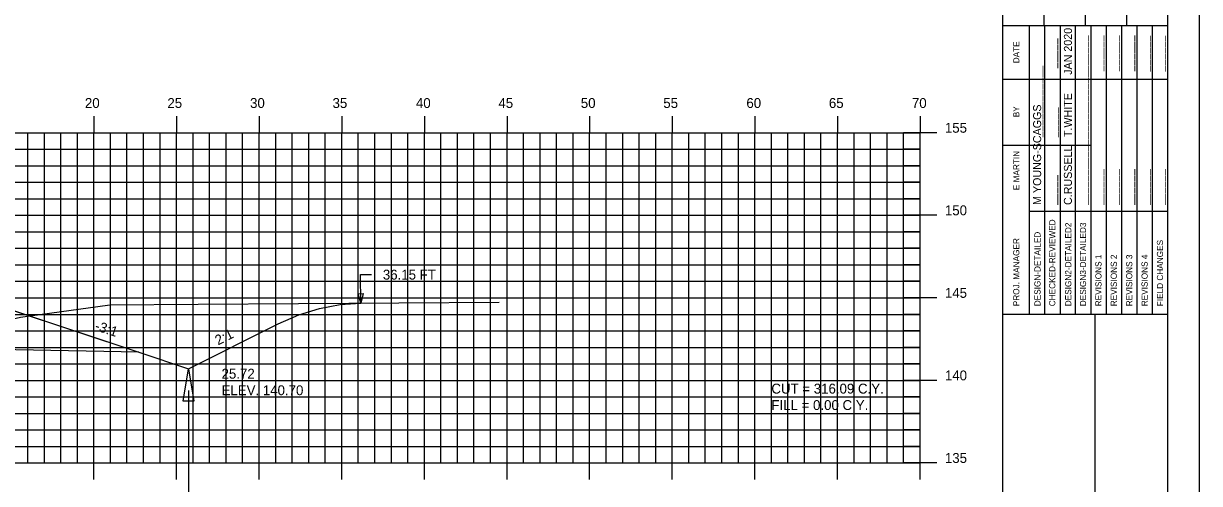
# Model space of a CAD drawing. Extents: x 1144972 to 1145142, y 608981 to 609091.
# Drawn here: x 1145071.1 to 1145142.3, y 609019.1 to 609047 of the extents above; entities that cross this region are included whole.
import ezdxf

# ---------------------------------------------------------------- set-up
doc = ezdxf.new("R2010")
doc.units = 0
for name, color, linetype in [('ANNOTATION', 7, 'Continuous'), ('BORDER', 7, 'Continuous'), ('D_Drainage_Ditch_Line', 7, 'Continuous'), ('D_Roadway_SlopeLines', 7, 'Continuous'), ('D_Roadway_SubGrade', 7, 'Continuous'), ('D_Text_Standard', 7, 'Continuous'), ('H_V ANNOTATION', 7, 'Continuous'), ('MAJOR', 7, 'Continuous'), ('MINOR', 7, 'Continuous'), ('PLOT BOUNDARY', 7, 'Continuous'), ('S_Roadway_Centerline', 7, 'Continuous')]:
    doc.layers.add(name, color=color, linetype=linetype)

msp = doc.modelspace()

# ---------------------------------------------------------------- linework, layer by layer
msp.add_lwpolyline([(1145018.151, 609030.592), (1145019.401, 609030.491), (1145020.651, 609030.24), (1145021.901, 609029.839), (1145023.151, 609029.289), (1145029.651, 609026.039), (1145032.651, 609027.039), (1145040.374, 609029.614), (1145040.375, 609029.614), (1145044.375, 609029.774), (1145055.375, 609029.994), (1145066.375, 609029.774), (1145070.375, 609029.614), (1145078.099, 609027.039), (1145081.099, 609026.039), (1145086.528, 609028.754), (1145087.778, 609029.302), (1145089.028, 609029.695), (1145090.278, 609029.934), (1145091.528, 609030.018)])
at = {"layer": 'BORDER'}
for p, q in [((1145130.376, 608984.335), (1145130.376, 609089.335)), ((1145132.876, 609046.838), (1145132.876, 609055.485)), ((1145135.376, 609046.838), (1145135.376, 609055.485)), ((1145137.876, 609046.838), (1145137.876, 609055.485)), ((1145130.376, 609046.838), (1145140.376, 609046.838)), ((1145130.376, 609029.338), (1145140.376, 609029.338)), ((1145135.967, 608994.338), (1145135.967, 609029.338))]:
    msp.add_line(p, q, dxfattribs=at)
msp.add_lwpolyline([(1144980.376, 608984.335), (1145140.376, 608984.335), (1145140.376, 609089.335), (1144980.376, 609089.335)], close=True, dxfattribs=at)
for points in [[(1145131.99, 609043.588), (1145131.99, 609046.838)], [(1145132.923, 609029.341), (1145132.923, 609046.838)], [(1145133.855, 609046.838), (1145133.855, 609029.341)], [(1145134.786, 609029.341), (1145134.786, 609046.838)], [(1145135.718, 609029.341), (1145135.718, 609046.838)], [(1145136.65, 609029.341), (1145136.65, 609046.838)], [(1145137.582, 609029.341), (1145137.582, 609046.838)], [(1145138.513, 609029.341), (1145138.513, 609046.838)], [(1145139.445, 609029.341), (1145139.445, 609046.838)], [(1145131.991, 609029.341), (1145131.991, 609046.132)], [(1145130.376, 609043.588), (1145140.376, 609043.588)], [(1145130.376, 609039.588), (1145131.991, 609039.588)], [(1145131.99, 609039.588), (1145135.717, 609039.588)], [(1145131.99, 609035.588), (1145140.376, 609035.588)]]:
    msp.add_lwpolyline(points, dxfattribs=at)
at = {"layer": 'D_Drainage_Ditch_Line'}
msp.add_line((1145081.099, 609024.727), (1145081.099, 609018.483), dxfattribs=at)
msp.add_lwpolyline([(1145081.427, 609024.071), (1145080.771, 609024.071), (1145081.099, 609026.039)], close=True, dxfattribs=at)
at = {"layer": 'D_Roadway_SlopeLines'}
for points in [[(1145081.099, 609026.039), (1145086.528, 609028.754), (1145087.778, 609029.302), (1145089.028, 609029.695), (1145090.278, 609029.934), (1145091.528, 609030.018)], [(1145078.099, 609027.039), (1145081.099, 609026.039)]]:
    msp.add_lwpolyline(points, dxfattribs=at)
at = {"layer": 'D_Roadway_SubGrade'}
msp.add_lwpolyline([(1145066.375, 609029.357), (1145066.375, 609029.524), (1145070.375, 609029.364), (1145070.375, 609029.614), (1145070.376, 609029.614), (1145078.099, 609027.039), (1145066.375, 609027.274)], close=True, dxfattribs=at)
at = {"layer": 'D_Text_Standard'}
msp.add_lwpolyline([(1145091.528, 609030.004), (1145091.5, 609031.74), (1145092.18, 609031.74)], dxfattribs=at)
msp.add_lwpolyline([(1145091.528, 609030.004), (1145091.373, 609030.583), (1145091.664, 609030.588)], close=True, dxfattribs=at)
at = {"layer": 'MAJOR'}
for p, q in [((1145075.375, 609041.337), (1145075.375, 609040.335)), ((1145080.375, 609041.337), (1145080.375, 609040.335)), ((1145085.375, 609041.337), (1145085.375, 609040.335)), ((1145090.375, 609041.337), (1145090.375, 609040.335)), ((1145095.375, 609041.337), (1145095.375, 609040.335)), ((1145100.375, 609041.337), (1145100.375, 609040.335)), ((1145105.375, 609041.337), (1145105.375, 609040.335)), ((1145110.375, 609041.337), (1145110.375, 609040.335)), ((1145115.375, 609041.337), (1145115.375, 609040.335)), ((1145120.375, 609041.337), (1145120.375, 609040.335)), ((1145125.375, 609041.337), (1145125.375, 609040.335)), ((1144985.375, 609040.335), (1145125.375, 609040.335)), ((1144985.375, 609040.335), (1145125.375, 609040.335)), ((1145075.375, 609020.335), (1145075.375, 609040.335)), ((1145080.375, 609020.335), (1145080.375, 609040.335)), ((1145085.375, 609020.335), (1145085.375, 609040.335)), ((1145090.375, 609020.335), (1145090.375, 609040.335)), ((1145095.375, 609020.335), (1145095.375, 609040.335)), ((1145100.375, 609020.335), (1145100.375, 609040.335)), ((1145105.375, 609020.335), (1145105.375, 609040.335)), ((1145110.375, 609020.335), (1145110.375, 609040.335)), ((1145115.375, 609020.335), (1145115.375, 609040.335)), ((1145120.375, 609020.335), (1145120.375, 609040.335)), ((1145126.377, 609040.335), (1145124.373, 609040.335)), ((1145125.375, 609020.335), (1145125.375, 609040.335)), ((1145125.375, 609020.335), (1145125.375, 609040.335)), ((1144985.375, 609035.335), (1145125.375, 609035.335)), ((1145126.377, 609035.335), (1145124.373, 609035.335)), ((1144985.375, 609030.335), (1145125.375, 609030.335)), ((1145126.377, 609030.335), (1145124.373, 609030.335)), ((1144985.375, 609025.335), (1145125.375, 609025.335)), ((1145126.377, 609025.335), (1145124.373, 609025.335)), ((1144985.375, 609020.335), (1145125.375, 609020.335)), ((1144985.375, 609020.335), (1145125.375, 609020.335)), ((1145075.375, 609019.333), (1145075.375, 609020.335)), ((1145080.375, 609019.333), (1145080.375, 609020.335)), ((1145085.375, 609019.333), (1145085.375, 609020.335)), ((1145090.375, 609019.333), (1145090.375, 609020.335)), ((1145095.375, 609019.333), (1145095.375, 609020.335)), ((1145100.375, 609019.333), (1145100.375, 609020.335)), ((1145105.375, 609019.333), (1145105.375, 609020.335)), ((1145110.375, 609019.333), (1145110.375, 609020.335)), ((1145115.375, 609019.333), (1145115.375, 609020.335)), ((1145120.375, 609019.333), (1145120.375, 609020.335)), ((1145126.377, 609020.335), (1145124.373, 609020.335)), ((1145125.375, 609019.333), (1145125.375, 609020.335))]:
    msp.add_line(p, q, dxfattribs=at)
at = {"layer": 'MINOR'}
for p, q in [((1145071.375, 609020.335), (1145071.375, 609040.335)), ((1145072.375, 609020.335), (1145072.375, 609040.335)), ((1145073.375, 609020.335), (1145073.375, 609040.335)), ((1145074.375, 609020.335), (1145074.375, 609040.335)), ((1145076.375, 609020.335), (1145076.375, 609040.335)), ((1145077.375, 609020.335), (1145077.375, 609040.335)), ((1145078.375, 609020.335), (1145078.375, 609040.335)), ((1145079.375, 609020.335), (1145079.375, 609040.335)), ((1145081.375, 609020.335), (1145081.375, 609040.335)), ((1145082.375, 609020.335), (1145082.375, 609040.335)), ((1145083.375, 609020.335), (1145083.375, 609040.335)), ((1145084.375, 609020.335), (1145084.375, 609040.335)), ((1145086.375, 609020.335), (1145086.375, 609040.335)), ((1145087.375, 609020.335), (1145087.375, 609040.335)), ((1145088.375, 609020.335), (1145088.375, 609040.335)), ((1145089.375, 609020.335), (1145089.375, 609040.335)), ((1145091.375, 609020.335), (1145091.375, 609040.335)), ((1145092.375, 609020.335), (1145092.375, 609040.335)), ((1145093.375, 609020.335), (1145093.375, 609040.335)), ((1145094.375, 609020.335), (1145094.375, 609040.335)), ((1145096.375, 609020.335), (1145096.375, 609040.335)), ((1145097.375, 609020.335), (1145097.375, 609040.335)), ((1145098.375, 609020.335), (1145098.375, 609040.335)), ((1145099.375, 609020.335), (1145099.375, 609040.335)), ((1145101.375, 609020.335), (1145101.375, 609040.335)), ((1145102.375, 609020.335), (1145102.375, 609040.335)), ((1145103.375, 609020.335), (1145103.375, 609040.335)), ((1145104.375, 609020.335), (1145104.375, 609040.335)), ((1145106.375, 609020.335), (1145106.375, 609040.335)), ((1145107.375, 609020.335), (1145107.375, 609040.335)), ((1145108.375, 609020.335), (1145108.375, 609040.335)), ((1145109.375, 609020.335), (1145109.375, 609040.335)), ((1145111.375, 609020.335), (1145111.375, 609040.335)), ((1145112.375, 609020.335), (1145112.375, 609040.335)), ((1145113.375, 609020.335), (1145113.375, 609040.335)), ((1145114.375, 609020.335), (1145114.375, 609040.335)), ((1145116.375, 609020.335), (1145116.375, 609040.335)), ((1145117.375, 609020.335), (1145117.375, 609040.335)), ((1145118.375, 609020.335), (1145118.375, 609040.335)), ((1145119.375, 609020.335), (1145119.375, 609040.335)), ((1145121.375, 609020.335), (1145121.375, 609040.335)), ((1145122.375, 609020.335), (1145122.375, 609040.335)), ((1145123.375, 609020.335), (1145123.375, 609040.335)), ((1145124.375, 609020.335), (1145124.375, 609040.335)), ((1144985.375, 609039.335), (1145125.375, 609039.335)), ((1145125.375, 609039.335), (1145124.373, 609039.335)), ((1144985.375, 609038.335), (1145125.375, 609038.335)), ((1145125.375, 609038.335), (1145124.373, 609038.335)), ((1144985.375, 609037.335), (1145125.375, 609037.335)), ((1145125.375, 609037.335), (1145124.373, 609037.335)), ((1144985.375, 609036.335), (1145125.375, 609036.335)), ((1145125.375, 609036.335), (1145124.373, 609036.335)), ((1144985.375, 609034.335), (1145125.375, 609034.335)), ((1145125.375, 609034.335), (1145124.373, 609034.335)), ((1144985.375, 609033.335), (1145125.375, 609033.335)), ((1145125.375, 609033.335), (1145124.373, 609033.335)), ((1144985.375, 609032.335), (1145125.375, 609032.335)), ((1145125.375, 609032.335), (1145124.373, 609032.335)), ((1144985.375, 609031.335), (1145125.375, 609031.335)), ((1145125.375, 609031.335), (1145124.373, 609031.335)), ((1144985.375, 609029.335), (1145125.375, 609029.335)), ((1145125.375, 609029.335), (1145124.373, 609029.335)), ((1144985.375, 609028.335), (1145125.375, 609028.335)), ((1145125.375, 609028.335), (1145124.373, 609028.335)), ((1144985.375, 609027.335), (1145125.375, 609027.335)), ((1145125.375, 609027.335), (1145124.373, 609027.335)), ((1144985.375, 609026.335), (1145125.375, 609026.335)), ((1145125.375, 609026.335), (1145124.373, 609026.335)), ((1144985.375, 609024.335), (1145125.375, 609024.335)), ((1145125.375, 609024.335), (1145124.373, 609024.335)), ((1144985.375, 609023.335), (1145125.375, 609023.335)), ((1145125.375, 609023.335), (1145124.373, 609023.335)), ((1144985.375, 609022.335), (1145125.375, 609022.335)), ((1145125.375, 609022.335), (1145124.373, 609022.335)), ((1144985.375, 609021.335), (1145125.375, 609021.335)), ((1145125.375, 609021.335), (1145124.373, 609021.335))]:
    msp.add_line(p, q, dxfattribs=at)
at = {"layer": 'PLOT BOUNDARY'}
msp.add_lwpolyline([(1144972.282, 608981.276), (1145142.282, 608981.276), (1145142.282, 609091.276), (1144972.282, 609091.276)], close=True, dxfattribs=at)
at = {"layer": 'S_Roadway_Centerline'}
msp.add_lwpolyline([(1145003.273, 609030.859), (1145005.674, 609030.858), (1145026.787, 609030.408), (1145027.556, 609030.232), (1145034.637, 609028.885), (1145034.944, 609028.954), (1145038.524, 609029.722), (1145040.621, 609029.878), (1145040.81, 609029.897), (1145041.855, 609029.932), (1145051.869, 609030.242), (1145062.239, 609030.04), (1145063.168, 609030.012), (1145063.576, 609029.981), (1145067.267, 609029.729), (1145070.324, 609029.106), (1145070.484, 609029.059), (1145070.938, 609029.17), (1145076.33, 609029.906), (1145081.681, 609029.961), (1145099.892, 609030.068)], dxfattribs=at)

# ---------------------------------------------------------------- texts
at = {"layer": 'ANNOTATION'}
for s, rotation, p in [('-3:1', 341.56521, (1145075.387, 609028.397)), ('2:1', 26.56505, (1145082.886, 609027.451))]:
    msp.add_text(s, height=0.6, rotation=rotation, dxfattribs=at).set_placement(p)
at = {"layer": 'BORDER'}
for s, height, p in [('JAN 2020', 0.4845, (1145134.562, 609043.843)), ('DATE', 0.3714, (1145131.38, 609044.544)), ('_____', 0.4845, (1145133.593, 609044.243)), ('______', 0.4845, (1145135.456, 609044.063)), ('______', 0.4845, (1145136.388, 609044.065)), ('______', 0.4845, (1145137.32, 609044.067)), ('______', 0.4845, (1145138.251, 609044.067)), ('______', 0.4845, (1145139.183, 609044.036)), ('______', 0.4845, (1145140.115, 609044.036)), ('____________', 0.48455, (1145132.699, 609040.073)), ('____________', 0.48455, (1145135.456, 609040.073)), ('T.WHITE', 0.4845, (1145134.562, 609040.073)), ('M YOUNG-SCAGGS', 0.48455, (1145132.699, 609035.961)), ('BY', 0.3714, (1145131.38, 609041.273)), ('_____', 0.4845, (1145133.63, 609040.073)), ('____________', 0.48455, (1145135.456, 609035.961)), ('E MARTIN', 0.3727, (1145131.38, 609036.855)), ('C.RUSSELL', 0.4845, (1145134.562, 609035.961)), ('_____', 0.4845, (1145133.593, 609035.961)), ('______', 0.4845, (1145136.388, 609035.961)), ('______', 0.4845, (1145137.32, 609035.961)), ('______', 0.4845, (1145138.251, 609035.961)), ('______', 0.4845, (1145139.183, 609035.961)), ('______', 0.4845, (1145140.115, 609035.961)), ('CHECKED-REVIEWED', 0.37275, (1145133.557, 609029.826)), ('DESIGN3-DETAILED3', 0.37275, (1145135.42, 609029.826)), ('DESIGN-DETAILED', 0.37275, (1145132.662, 609029.826)), ('DESIGN2-DETAILED2', 0.37275, (1145134.526, 609029.826)), ('PROJ. MANAGER', 0.37275, (1145131.38, 609029.826)), ('FIELD CHANGES', 0.37275, (1145140.078, 609029.826)), ('REVISIONS 1', 0.37275, (1145136.352, 609029.826)), ('REVISIONS 2', 0.37275, (1145137.283, 609029.826)), ('REVISIONS 3', 0.37275, (1145138.215, 609029.826)), ('REVISIONS 4', 0.37275, (1145139.147, 609029.826))]:
    msp.add_text(s, height=height, rotation=90, dxfattribs=at).set_placement(p)
at = {"layer": 'D_Text_Standard'}
for s, p in [('36.15 FT', (1145092.86, 609031.44)), ('25.72', (1145083.099, 609025.439)), ('ELEV. 140.70', (1145083.099, 609024.437)), ('CUT = 316.09 C.Y.', (1145116.375, 609024.535)), ('FILL = 0.00 C.Y.', (1145116.375, 609023.539))]:
    msp.add_text(s, height=0.6, dxfattribs=at).set_placement(p)
at = {"layer": 'H_V ANNOTATION'}
for s, p in [('20', (1145074.829, 609041.835)), ('25', (1145079.821, 609041.835)), ('30', (1145084.824, 609041.835)), ('35', (1145089.816, 609041.835)), ('40', (1145094.862, 609041.835)), ('45', (1145099.854, 609041.835)), ('50', (1145104.84, 609041.835)), ('55', (1145109.832, 609041.835)), ('60', (1145114.862, 609041.835)), ('65', (1145119.854, 609041.835)), ('70', (1145124.878, 609041.835)), ('155', (1145126.875, 609040.335)), ('150', (1145126.875, 609035.335)), ('145', (1145126.875, 609030.335)), ('140', (1145126.875, 609025.335)), ('135', (1145126.875, 609020.335))]:
    msp.add_text(s, height=0.6, dxfattribs=at).set_placement(p)

doc.saveas('drawing.dxf')
